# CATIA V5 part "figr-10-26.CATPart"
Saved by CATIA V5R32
Part number: Part1
Bounding box of the stored display mesh (mm): x -65.919 to 25.581, y -200.404 to 0.194, z 0 to 71.635
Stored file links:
  D:\PROJECTS\Project 2022\CATIA V5 6R 2022\Resources\Part Files\c10_catia_v5_6r2022_prt\c10_catia_v5_6r2022_prt\figr-10-26.CATPart
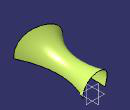
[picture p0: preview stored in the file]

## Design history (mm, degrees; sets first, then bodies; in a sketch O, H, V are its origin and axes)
Set1
  Sketch1 on xy-plane, origin (0, 0, 0), H (1, 0, 0), V (0, 1, 0)
    spline S1 through (-36.6295, 0) (-39.5961, -76.7629) (-56.6868, -154.7631) (-92.5015, -194.2587)
    point P1 (-36.6295, 0)
    coincidence: P1 H
  Sketch2 on xy-plane, origin (0, 0, 0), H (1, 0, 0), V (0, 1, 0)
    spline S1 through (25.5807, 0) (5.5021, -50.6307) (25.5807, -200.404)
    point P1 (25.5807, 0)
    coincidence: P1 H
  Sketch3 on zx-plane, origin (0, 0, 0), H (-1, 0, 0), V (0, 0, 1)
    spline S1 through (-25.5807, 0) (16.4189, 47.2175) (28.9802, 46.33) (36.6295, 0)
    reference projected point E1 (36.6295, 0) from vertex of Sketch1
    reference projected point E2 (-25.5807, 0) from vertex of Sketch2
    point P1 (-25.5807, 0)
    point P2 (36.6295, 0)
    coincidence: P1 H, P2 H, E1 P2, P1 E2
  Sweep1: type Unspec, Profile Sketch3, Guide (Sketch1; Sketch2), FittingPoints (vertex of Sketch1; vertex of Sketch2)
Body1 (main body)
